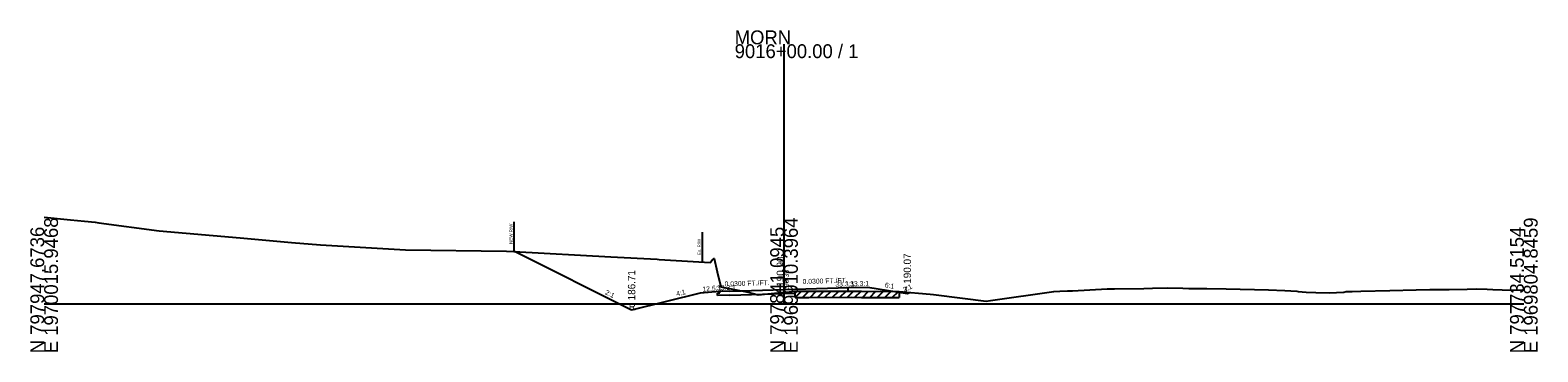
# Model space of a CAD drawing. Extents: x -26 to 2313, y -1511 to 5559.
# Drawn here: x 997.2 to 1302.8, y 1990.3 to 2055.4 of the extents above; entities that cross this region are included whole.
import ezdxf

# ---------------------------------------------------------------- set-up
doc = ezdxf.new("R2010")
doc.units = 0
for name, color, linetype in [('RD_GPK_XS_Cell', 7, 'Continuous'), ('RD_XS_Base', 7, 'Continuous'), ('RD_XS_EarthShd', 7, 'Continuous'), ('RD_XS_ExGround', 7, 'Continuous'), ('RD_XS_ExPaveRet', 7, 'Continuous'), ('RD_XS_ExRW', 7, 'Continuous'), ('RD_XS_Misc_Line', 7, 'Continuous'), ('RD_XS_NewRW', 7, 'Continuous'), ('RD_XS_Pave', 7, 'Continuous'), ('RD_XS_PaveOvlay', 7, 'Continuous'), ('RD_XS_PaveShd', 7, 'Continuous'), ('RD_XS_TieSlope', 7, 'Continuous'), ('RD_XS_TX_Elev_EX', 7, 'Continuous'), ('RD_XS_TX_Elev_PR', 7, 'Continuous'), ('RD_XS_TX_Misc', 7, 'Continuous'), ('RD_XS_TX_MkPT', 7, 'Continuous'), ('RD_XS_TX_Profile', 7, 'Continuous'), ('RD_XS_TX_ShdSlope', 7, 'Continuous'), ('RD_XS_TX_Slope', 7, 'Continuous')]:
    doc.layers.add(name, color=color, linetype=linetype)

msp = doc.modelspace()

# ---------------------------------------------------------------- linework, layer by layer
at = {"layer": 'RD_GPK_XS_Cell'}
for p, q in [((1150, 2000), (1150, 2052.52)), ((1000, 2000), (1150, 2000)), ((1150, 2000), (1300, 2000))]:
    msp.add_line(p, q, dxfattribs=at)
at = {"layer": 'RD_XS_Base'}
for p, q in [((1137, 2002.21), (1137, 2002.51)), ((1163, 2002.59), (1163, 2003.29)), ((1136.5, 2002.19), (1137, 2002.21)), ((1136.5, 2001.71), (1136.5, 2002.19)), ((1139, 2001.79), (1136.5, 2001.71)), ((1139, 2001.79), (1150, 2002.12)), ((1150, 2002.12), (1152.25, 2002.18))]:
    msp.add_line(p, q, dxfattribs=at)
at = {"layer": 'RD_XS_EarthShd'}
for p, q in [((1137, 2002.51), (1133, 2002.19)), ((1163, 2003.29), (1167, 2003.41))]:
    msp.add_line(p, q, dxfattribs=at)
at = {"layer": 'RD_XS_ExGround'}
msp.add_lwpolyline([(1000, 2017.51), (1005.36, 2016.99), (1008.2, 2016.71), (1010.34, 2016.5), (1011.07, 2016.42), (1023.33, 2014.81), (1039.75, 2013.36), (1050.16, 2012.43), (1056.05, 2011.96), (1073.27, 2010.96), (1093.73, 2010.64), (1095.24, 2010.58), (1114.91, 2009.53), (1124.3, 2009.02), (1124.7, 2009.01), (1135, 2008.39), (1135.45, 2008.81), (1135.86, 2009.19), (1136.46, 2006.46), (1137.21, 2003.46), (1142.72, 2002.37), (1144.79, 2001.84), (1150, 2002.35), (1151.05, 2002.45), (1152.25, 2002.56), (1155.01, 2002.57), (1163.73, 2002.59), (1165.7, 2002.57), (1173.38, 2002.51), (1179.63, 2001.94), (1180.33, 2001.87), (1180.83, 2001.82), (1190.97, 2000.57), (1191.85, 2000.69), (1204.7, 2002.47), (1205.89, 2002.54), (1207.5, 2002.61), (1208.52, 2002.66), (1215.52, 2003.02), (1217.03, 2003.04), (1222.95, 2003.14), (1224.72, 2003.17), (1227.68, 2003.23), (1230.86, 2003.16), (1232.1, 2003.14), (1235.71, 2003.08), (1239.65, 2003.02), (1248.23, 2002.81), (1251.55, 2002.73), (1252.78, 2002.65), (1253.99, 2002.59), (1254.23, 2002.47), (1255.88, 2002.37), (1257.83, 2002.27), (1260.54, 2002.26), (1263.51, 2002.36), (1263.95, 2002.48), (1265.16, 2002.52), (1266.96, 2002.59), (1272.81, 2002.73), (1278.15, 2002.86), (1280.93, 2002.89), (1284.83, 2002.94), (1288.53, 2003), (1290.48, 2003.03), (1292.54, 2002.95), (1293.7, 2002.9), (1295.63, 2002.86), (1300, 2002.76)], dxfattribs=at)
at = {"layer": 'RD_XS_ExPaveRet'}
for p, q in [((1152.25, 2001.31), (1152.25, 2002.56)), ((1173.38, 2002.51), (1173.38, 2001.26)), ((1152.25, 2001.31), (1155.01, 2001.32)), ((1155.01, 2001.32), (1163.73, 2001.34)), ((1163.73, 2001.34), (1165.7, 2001.32)), ((1165.7, 2001.32), (1173.38, 2001.26))]:
    msp.add_line(p, q, dxfattribs=at)
at = {"layer": 'RD_XS_ExRW'}
msp.add_line((1133.38, 2014.49), (1133.38, 2008.49), dxfattribs=at)
at = {"layer": 'RD_XS_Misc_Line'}
for p, q in [((1152.25, 2001.31), (1153.52, 2002.56)), ((1153.77, 2001.31), (1155.03, 2002.57)), ((1155.28, 2001.32), (1156.55, 2002.57)), ((1156.8, 2001.32), (1158.06, 2002.57)), ((1158.31, 2001.33), (1159.58, 2002.58)), ((1159.83, 2001.33), (1161.09, 2002.58)), ((1161.34, 2001.33), (1162.61, 2002.59)), ((1162.86, 2001.34), (1164.12, 2002.59)), ((1164.37, 2001.33), (1165.63, 2002.58)), ((1165.89, 2001.32), (1167.14, 2002.56)), ((1167.4, 2001.31), (1168.65, 2002.55)), ((1168.92, 2001.3), (1170.17, 2002.54)), ((1170.43, 2001.28), (1171.68, 2002.52)), ((1171.95, 2001.27), (1173.2, 2002.51))]:
    msp.add_line(p, q, dxfattribs=at)
at = {"layer": 'RD_XS_NewRW'}
msp.add_line((1095.24, 2016.58), (1095.24, 2010.58), dxfattribs=at)
at = {"layer": 'RD_XS_Pave'}
for p, q in [((1139, 2002.57), (1150, 2002.9)), ((1150, 2002.9), (1161, 2003.23))]:
    msp.add_line(p, q, dxfattribs=at)
at = {"layer": 'RD_XS_PaveOvlay'}
for p, q in [((1152.25, 2002.56), (1155.01, 2002.57)), ((1152.25, 2002.56), (1152.25, 2002.18)), ((1155.01, 2002.57), (1163, 2002.59))]:
    msp.add_line(p, q, dxfattribs=at)
at = {"layer": 'RD_XS_PaveShd'}
for p, q in [((1139, 2002.57), (1137, 2002.51)), ((1161, 2003.23), (1163, 2003.29))]:
    msp.add_line(p, q, dxfattribs=at)
at = {"layer": 'RD_XS_TieSlope'}
for p, q in [((1119.1, 1998.71), (1095.36, 2010.58)), ((1167, 2003.41), (1175, 2002.07)), ((1175, 2002.07), (1175.49, 2002.32)), ((1133, 2002.19), (1119.1, 1998.71))]:
    msp.add_line(p, q, dxfattribs=at)

# ---------------------------------------------------------------- texts
at = {"layer": 'RD_GPK_XS_Cell'}
for s, p in [('MORN', (1140, 2052.52)), ('9016+00.00 / 1', (1140, 2049.72))]:
    msp.add_text(s, height=2.8, dxfattribs=at).set_placement(p)
for s, p in [('N 797947.6736', (1000, 1990)), ('E 1970015.9468', (1002.8, 1990)), ('N 797841.0945', (1150, 1990)), ('E 1969910.3964', (1152.8, 1990)), ('N 797734.5154', (1300, 1990)), ('E 1969804.8459', (1302.8, 1990))]:
    msp.add_text(s, height=2.8, rotation=90, dxfattribs=at).set_placement(p)
at = {"layer": 'RD_XS_ExRW'}
msp.add_text('Ex. R/W ', height=0.65, rotation=90, dxfattribs=at).set_placement((1133.13, 2009.87))
at = {"layer": 'RD_XS_NewRW'}
msp.add_text('NEW R/W ', height=0.65, rotation=90, dxfattribs=at).set_placement((1094.98, 2012.14))
at = {"layer": 'RD_XS_TX_Elev_EX'}
msp.add_text('190.35', height=1, rotation=90, dxfattribs=at).set_placement((1150.98, 2002.64))
at = {"layer": 'RD_XS_TX_Elev_PR'}
msp.add_text(' 190.90', height=1.5, rotation=90, dxfattribs=at).set_placement((1150, 2002.9))
at = {"layer": 'RD_XS_TX_Misc'}
for s, p in [('190.07', (1175.75, 2004.07)), ('186.71', (1119.85, 2000.71))]:
    msp.add_text(s, height=1.5, rotation=90, dxfattribs=at).set_placement(p)
at = {"layer": 'RD_XS_TX_MkPT'}
for s, p in [('L', (1174.49, 2002.07)), ('R', (1118.51, 1998.71))]:
    msp.add_text(s, height=1.5, dxfattribs=at).set_placement(p)
at = {"layer": 'RD_XS_TX_Profile'}
for p in [(1136.42, 2002.74), (1160.42, 2003.46)]:
    msp.add_text('33.3:1', height=1, rotation=1.7184, dxfattribs=at).set_placement(p)
at = {"layer": 'RD_XS_TX_ShdSlope'}
for s, rotation, p in [('12.5:1', 4.5739, (1133.5, 2002.48)), ('33.3:1', 1.7184, (1163.42, 2003.55))]:
    msp.add_text(s, height=1, rotation=rotation, dxfattribs=at).set_placement(p)
at = {"layer": 'RD_XS_TX_Slope'}
for s, rotation, p in [('2:1', 333.4349, (1113.62, 2002.01)), ('4:1', 14.0362, (1128.26, 2001.52)), ('0.0300 FT./FT.', 1.7184, (1137.97, 2003.53)), ('0.0300 FT./FT.', 1.7184, (1153.78, 2004.01)), ('6:1', 350.5377, (1170.38, 2003.35)), ('2:1', 26.5651, (1174.39, 2002.33))]:
    msp.add_text(s, height=1, rotation=rotation, dxfattribs=at).set_placement(p)

doc.saveas('drawing.dxf')
